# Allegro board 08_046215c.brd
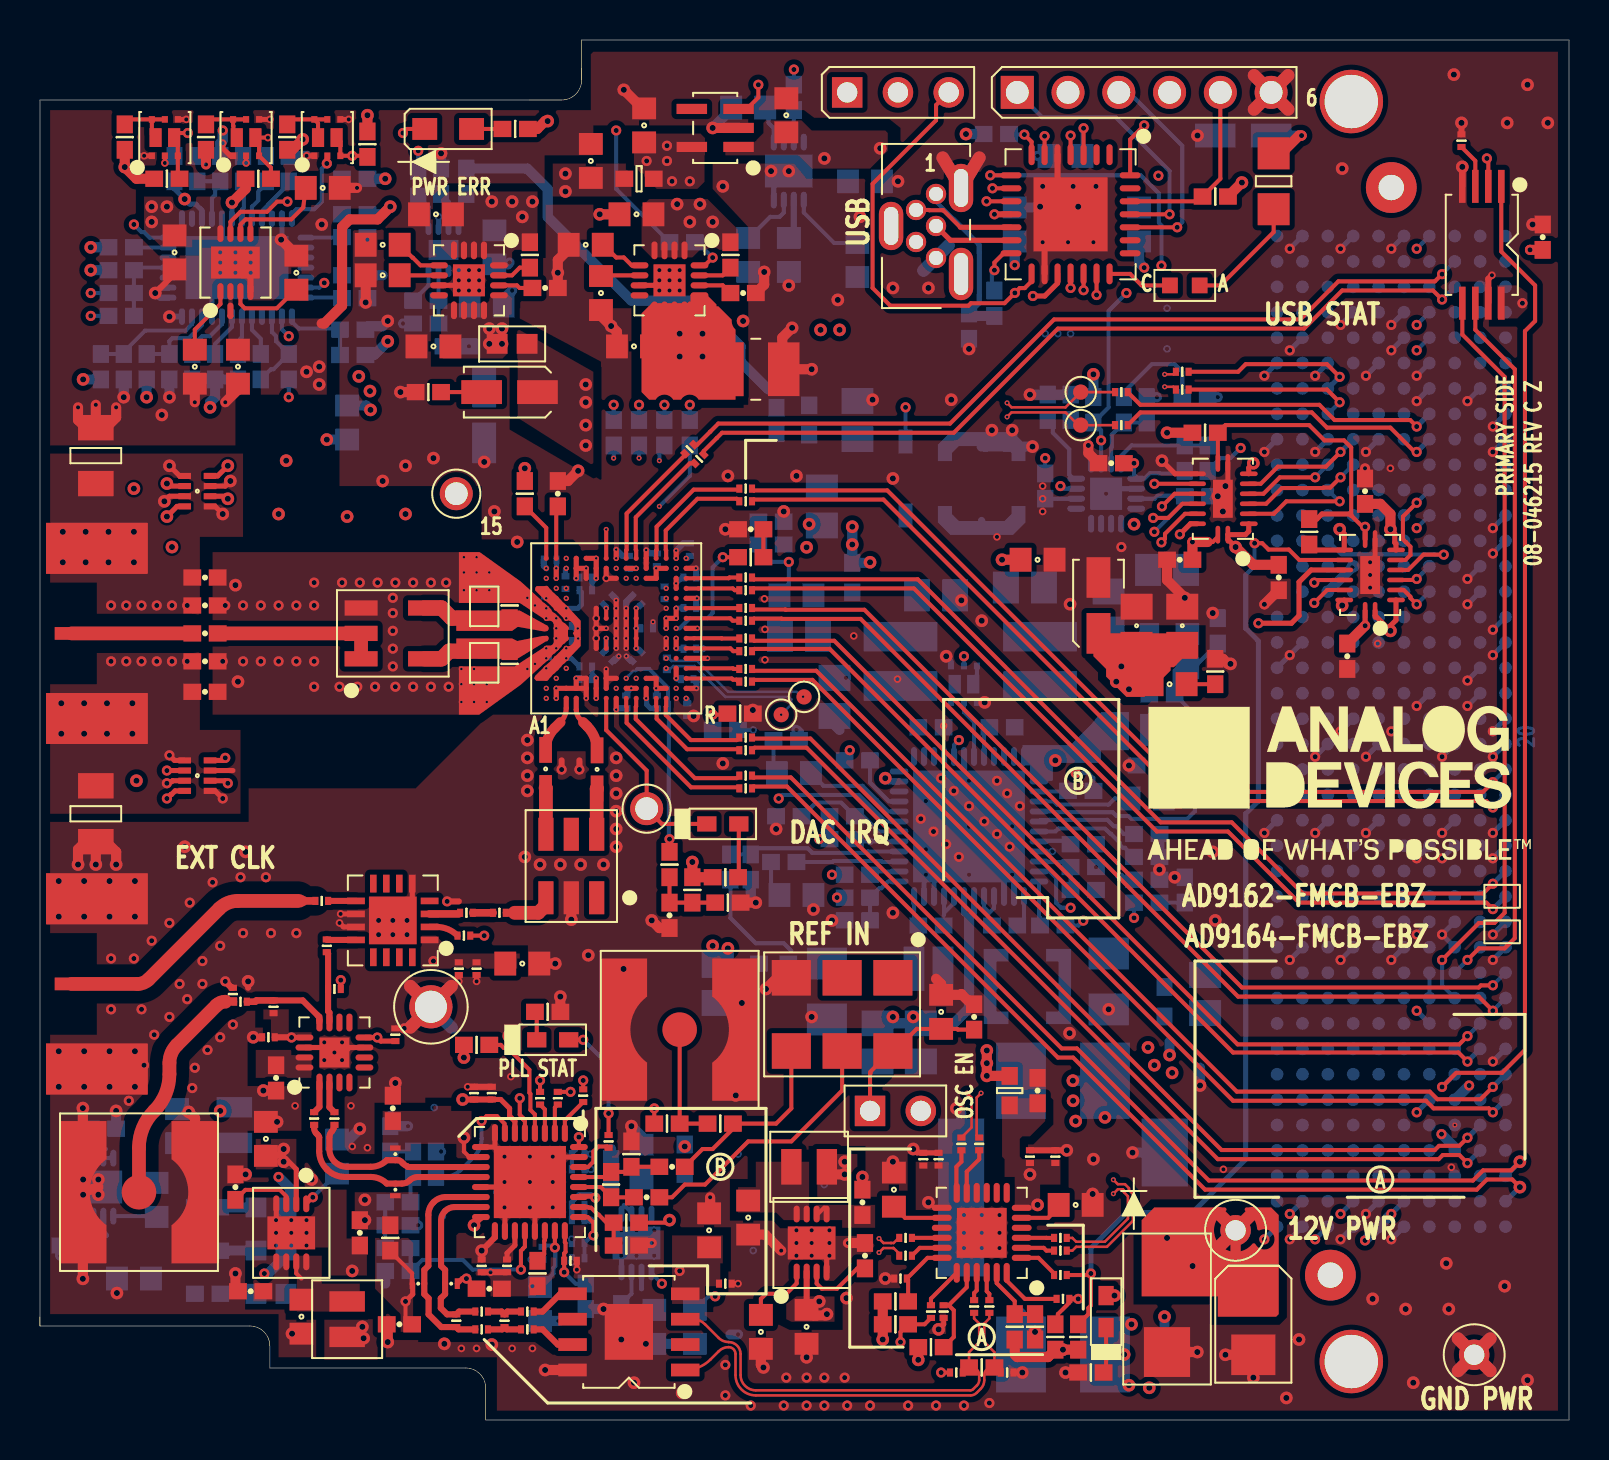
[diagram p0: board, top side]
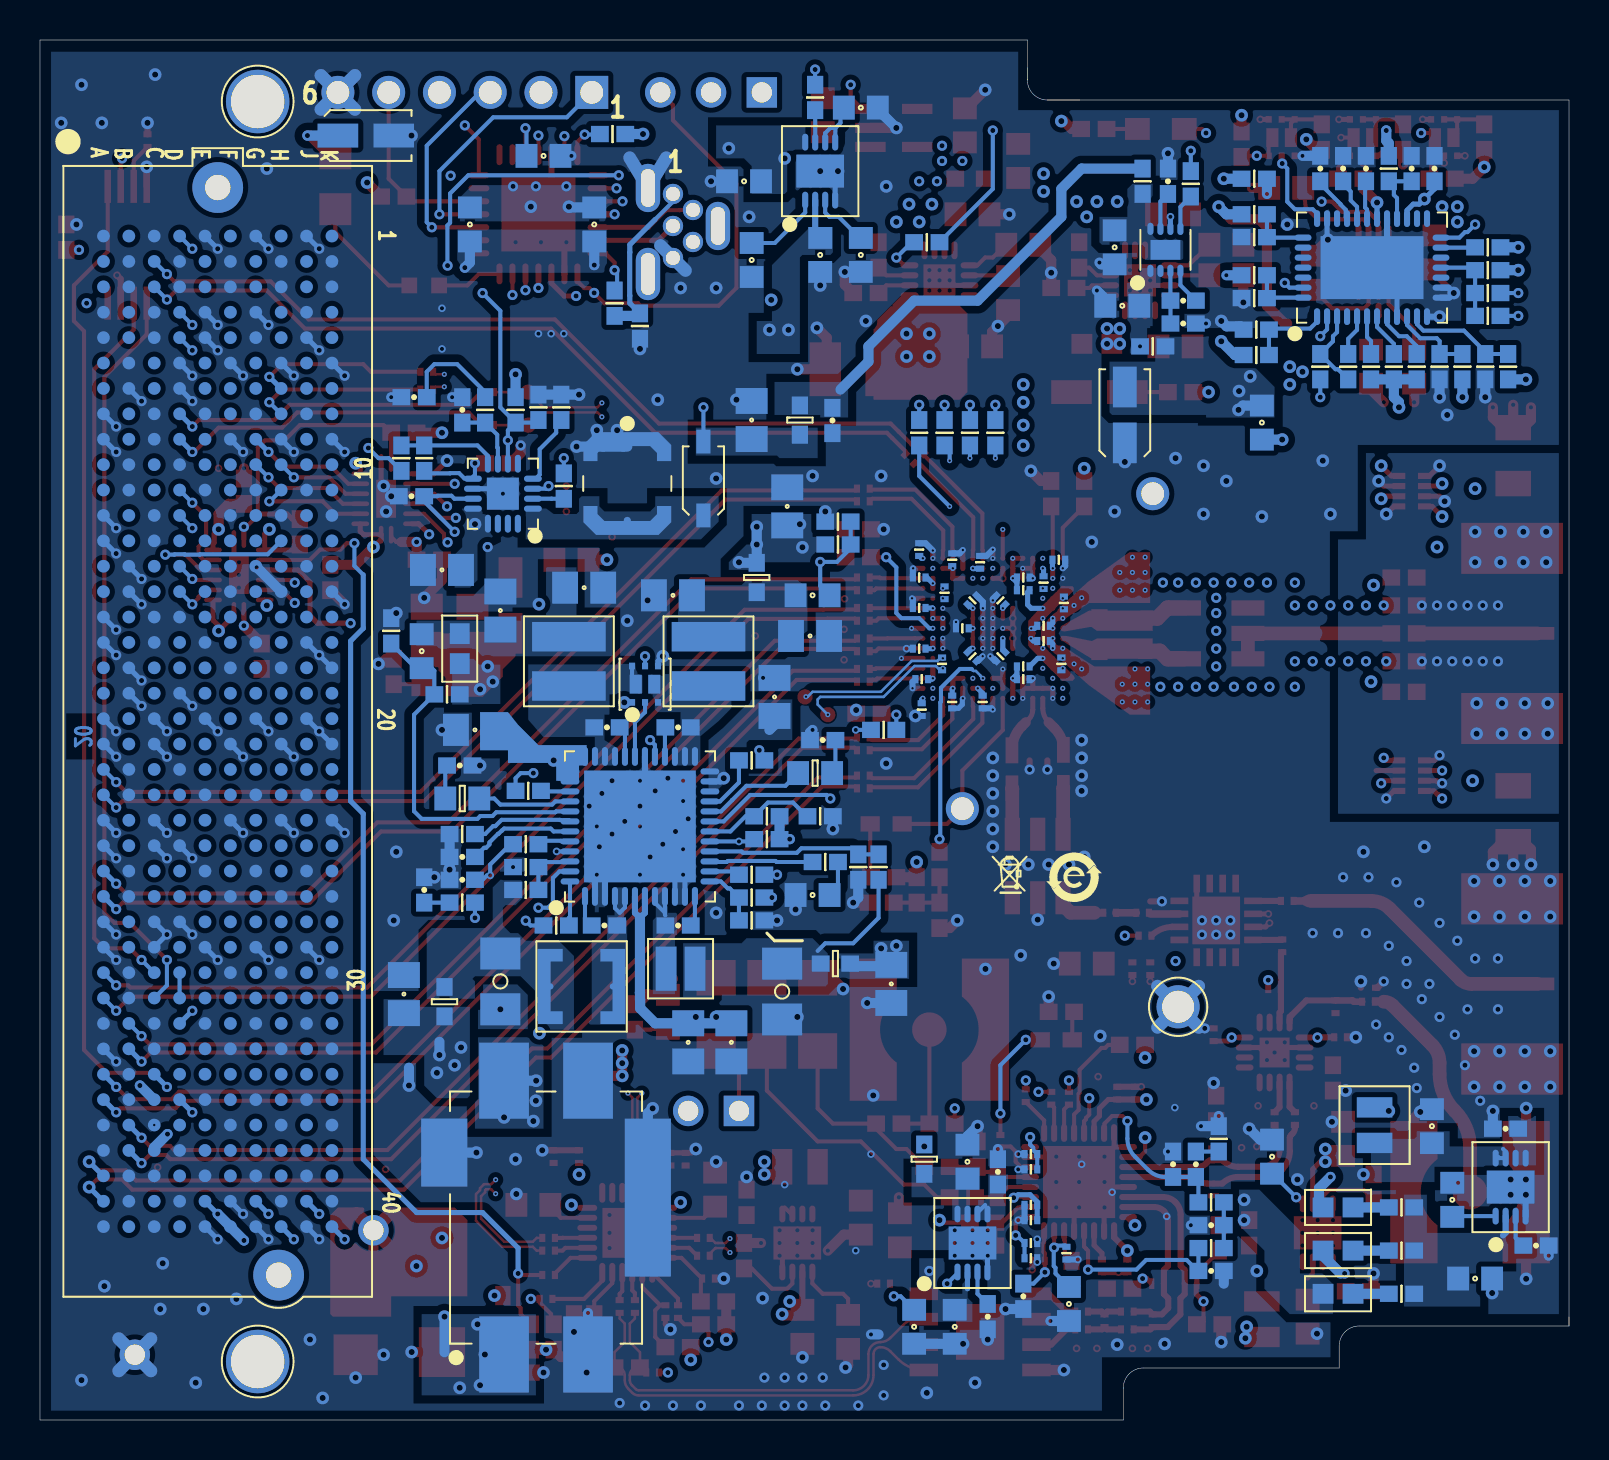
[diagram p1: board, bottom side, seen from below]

Outline 76.5 x 69 mm; copper layers: TOP, L2_GROUND, L3_SIGNAL, L4_GROUND, L5_POWER, L6_POWER, L7_GROUND, L8_POWER, L9_GROUND, L10_SIGNAL, L11_GROUND, BOTTOM. Coordinates in mm from the lower left corner of the outline.
Outline path: 26.1,66 0,66 0,4.7 ; 0,4.7 0,5.16 ; 0,4.7 10.5,4.7 arc(11.21,4.41) 11.5,3.7 11.5,2.6 21.3,2.6 arc(22.01,2.31) 22.3,1.6 22.3,0 76.5,0 76.5,69 27.1,69 27.1,67 ; 24.5,66 24.5,66 26.1,66 arc(26.81,66.29) 27.1,67 27.1,67.6

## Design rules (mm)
constraint set DEFAULT: min track width 0.203, pair gap 0.203
net group ADF4355OUTA: nets ADF4355OUTA ADF4355OUTAB
net group ADF4355OUTB: nets ADF4355OUTB ADF4355OUTBB
net group CLK: nets CLK_N CLK_P
net group DP2: nets UNNAMED_5_CAP_I292_N1 UNNAMED_5_CAP_I293_N1
net group DP5: nets UNNAMED_5_CAP_I90_N1 UNNAMED_5_CAP_I294_N1
net group GBTCLK0_M2C: nets GBTCLK0_M2C_N GBTCLK0_M2C_P
net group HMC365OUT: nets HMC365OUT HMC365OUTB
net group OUT: nets OUT_N OUT_P
net group SERDIN0_N: nets SERDIN0_N UNNAMED_7_CAP_I176_N2
net group SERDIN0_P: nets SERDIN0_P UNNAMED_7_CAP_I177_N2
net group SERDIN1_N: nets SERDIN1_N UNNAMED_7_CAP_I166_N2
net group SERDIN1_P: nets SERDIN1_P UNNAMED_7_CAP_I167_N2
net group SERDIN2_N: nets SERDIN2_N UNNAMED_7_CAP_I168_N2
net group SERDIN2_P: nets SERDIN2_P UNNAMED_7_CAP_I169_N2
net group SERDIN3_N: nets SERDIN3_N UNNAMED_7_CAP_I170_N2
net group SERDIN3_P: nets SERDIN3_P UNNAMED_7_CAP_I171_N2
net group SERDIN4_N: nets SERDIN4_N UNNAMED_7_CAP_I162_N2
net group SERDIN4_P: nets SERDIN4_P UNNAMED_7_CAP_I163_N2
net group SERDIN5_N: nets SERDIN5_N UNNAMED_7_CAP_I173_N2
net group SERDIN5_P: nets SERDIN5_P UNNAMED_7_CAP_I172_N2
net group SERDIN6_N: nets SERDIN6_N UNNAMED_7_CAP_I164_N2
net group SERDIN6_P: nets SERDIN6_P UNNAMED_7_CAP_I165_N2
net group SERDIN7_N: nets SERDIN7_N UNNAMED_7_CAP_I175_N2
net group SERDIN7_P: nets SERDIN7_P UNNAMED_7_CAP_I174_N2
net group SYNC: nets SYNC_N SYNC_P
net group SYSREF: nets SYSREF_N SYSREF_P
net group SYSREF2: nets SYSREF2_N SYSREF2_P
net group UNNAMED_3_CAP_I1318_N1: nets UNNAMED_3_CAP_I1318_N1 UNNAMED_3_CAP_I1318_N2
nets with their own width: min track width 0.203; nets ADF4355_VDD_3V3 ADF4355_VRF_3V3 UNNAMED_4_ADP5054_I1011_VDD USB_VCC
nets with their own width: min track width 0.254; nets USB_D+ USB_D-

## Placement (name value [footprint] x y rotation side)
C1  1000pF  [C0402]  8.26 42.12 0 top
C2  0.1uF  [C0201]  29.84 40.98 135 bottom
C3  0.1uF  [C0201]  28.45 40.98 45 bottom
C4  100pF  [C0201]  10.03 20.92 180 top
C5  1000pF  [C0402]  8.26 36.41 0 top
C6  4.7uF  [C0603]  37.34 65.24 90 top
C7  1uF  [C0402]  31.5 25.23 270 top
C8  0.1uF  [C0201]  26.29 41.87 90 bottom
C9  4.7uF  [C0603]  30.23 64.73 90 top
C10  0.1uF  [C0402]  48.13 34.63 0 bottom
C11  0.0033uF  [C0603]  57.4 38.44 90 bottom
C12  47uF  [C0805H60]  49.28 41.62 180 bottom
C13  0.0033uF  [C0603]  37.85 41.24 0 bottom
C14  1000pF  [C0402]  8.26 39.33 0 top
C15  47uF  [C0805H60]  44.83 41.24 0 bottom
C16  10uF  [C0805]  57.15 39.71 270 top
C17  10uF  [C0805]  54.86 39.71 270 top
C18  22uF  [C0603]  56.52 36.79 0 top
C19  22uF  [C0805]  39.12 45.68 90 bottom
C20  0.1uF  [C0201]  32.51 42.12 0 bottom
C21  1uF  [C0402]  35.56 44.54 180 top
C22  0.01UF  [C0402]  25.27 56.6 0 top
C23  1uF  [C0402]  25.91 46.32 90 top
C24  0.01UF  [C0402]  35.18 56.35 0 top
C25  1uF  [C0603]  17.14 58.76 180 top
C26  0.1uF  [C0201]  30.86 35.9 270 bottom
C27  1uF  [C0603]  27.3 58.76 180 top
C28  10uF  [C0603]  19.81 60.29 180 top
C29  10uF  [C0603]  29.84 60.29 180 top
C30  1uF  [C0603]  17.14 57.24 180 top
C31  0.1uF  [C0201]  32.51 40.6 0 bottom
C32  0.047uF  [C0508IDC]  7.87 32.22 90 top
C33  0.047uF  [C0508IDC]  7.87 46.44 270 top
C34  100pF  [C0201]  14.1 25.95 0 top
C35  1000pF  [C0402]  8.26 37.93 0 top
C36  1000pF  [C0402]  8.26 40.73 0 top
C37  0.1uF  [C0201]  32.51 38.57 0 bottom
C38  100pF  [C0201]  21.34 25.36 180 top
C39  100pF  [C0201]  14.35 23.71 90 top
C40  1uF  [C0603]  28.07 56.35 270 top
C41  10uF  [C0805]  54.74 34.5 180 bottom
C42  10uF  [C0805]  39.75 36.16 270 bottom
C43  0.1uF  [C0201]  32.39 37.04 0 bottom
C44  10uF  [C0805]  44.07 18.88 90 bottom
C45  10uF  [C0805]  41.91 18.88 90 bottom
C46  0.039uF  [C0603]  37.85 26.25 180 bottom
C47  0.018uF  [C0402]  55.5 32.73 0 bottom
C48  0.0047uF  [C0402]  37.34 34 180 bottom
C49  0.018uF  [C0402]  57.28 26.5 270 bottom
C50  10uF  [C0603]  19.69 53.68 180 top
C51  10uF  [C0603]  7.75 52.67 270 top
C52  10uF  [C0603]  29.72 53.68 180 top
C53  47uF  [C0805H60]  53.47 40.47 90 bottom
C54  47uF  [C0805H60]  37.97 39.2 180 bottom
C55  1uF  [C0603]  12.83 57.36 90 top
C56  10uF  [C0603]  6.73 58.38 270 top
C57  1UF  [C0402]  7.87 62.57 90 bottom
C58  1UF  [C0402]  6.73 62.57 90 bottom
C59  4.7uF  [C0603]  27.56 62.95 90 top
C60  2.2uF  [C0402]  11.3 62.57 90 bottom
C61  0.0012uF  [C0402]  19.81 12.79 270 bottom
C62  0.039uF  [C0402]  18.67 12.79 90 bottom
C63  100pF  [C0402]  46.74 20.15 270 top
C64  0.022uF  [C0402]  10.16 62.57 90 bottom
C65  1uF  [C0603]  45.09 20.41 270 top
C66  390pF  [C0402]  17.91 9.74 180 bottom
C67  0.047uF  [C0402]  12.45 62.57 90 bottom
C69  10pF  [C0402]  17.91 7.45 0 bottom
C71  0.1uF  [C0402]  66.29 46.44 90 top
C72  0.1uF  [C0402]  61.98 42.12 270 top
C76  0.1uF  [C0402]  57.02 43.01 180 top
C77  100pF  [C0402]  65.41 38.19 270 top
C81  0.1uF  [C0201]  35.31 46.57 0 top
C82  0.1uF  [C0201]  35.31 45.93 0 top
C83  0.1uF  [C0201]  35.31 42.12 0 top
C84  0.1uF  [C0201]  35.31 41.49 0 top
C85  0.1uF  [C0201]  35.31 40.6 0 top
C86  0.1uF  [C0201]  35.31 39.97 0 top
C87  0.1uF  [C0201]  35.31 37.55 0 top
C88  0.1uF  [C0201]  35.31 36.92 0 top
C89  0.1uF  [C0201]  35.31 32.22 0 top
C310  10uF  [C0603]  32.77 4.66 90 bottom
C311  100pF  [C0201]  21.84 22.57 90 top
C312  1uF  [C0402]  29.08 5.17 90 bottom
C313  10uF  [C0603]  30.1 12.91 270 bottom
C314  0.1uF  [C0201]  20.95 22.57 270 top
C315  1uF  [C0402]  28.57 12.41 270 bottom
C316  0.47uF  [C0603]  24.13 22.82 0 top
C317  10uF  [C0603]  30.73 4.66 90 bottom
C323  1uF  [C0402]  49.91 16.47 270 top
C325  0.47uF  [C0603]  51.82 10.76 180 top
C326  0.47uF  [C0603]  42.72 11.52 90 top
C327  0.1uF  [C0201]  44.2 13.04 90 top
C328  0.1uF  [C0201]  44.96 13.04 90 top
C330  0.1uF  [C0201]  50.8 13.17 90 top
C331  0.1uF  [C0201]  49.53 13.17 90 top
C333  0.1uF  [C0201]  51.05 8.47 0 top
C334  0.1uF  [C0201]  51.05 9.1 0 top
C338  10uF  [C0603]  33.48 9.49 270 top
C339  0.001uF  [C0201]  34.29 6.82 0 top
C340  100pF  [C0201]  47.5 5.68 90 top
C341  100pF  [C0201]  46.74 5.68 90 top
C344  0.1uF  [C0201]  46.99 13.8 90 top
C345  0.1uF  [C0201]  46.1 13.8 90 top
C346  0.1uF  [C0201]  43.31 9.1 180 top
C347  0.1uF  [C0201]  43.31 8.22 180 top
C348  2400PF  [C0803H60]  25.3 32.55 90 top
C349  2400PF  [C0803H60]  27.87 32.53 90 top
C410  1uF  [C0402]  55.37 27.01 180 bottom
C411  1uF  [C0402]  55.37 28.15 180 bottom
C412  0.1uF  [C0402]  44.58 34.63 180 bottom
C413  0.1uF  [C0402]  48.26 24.73 180 bottom
C415  0.1uF  [C0402]  44.58 24.73 0 bottom
C419  22uF  [C0805]  33.91 21.8 90 bottom
C420  22uF  [C0805]  58.29 21.3 270 bottom
C424  22uF  [C0805]  40.89 50 270 bottom
C426  4.7uF  [C0603]  22.73 58.63 270 bottom
C427  1UF  [C0402]  20.07 61.94 270 bottom
C429  1UF  [C0402]  53.59 47.84 0 top
C430  1UF  [C0402]  57.91 46.19 180 bottom
C432  4.7uF  [C0603]  22.35 55.71 180 bottom
C433  2.2uF  [C0805]  56.39 42.51 0 bottom
C434  1UF  [C0402]  19.3 55.97 0 bottom
C435  1UF  [C0402]  19.3 54.82 180 bottom
C436  1uF  [C0402]  55.37 50.51 90 bottom
C437  0.047uF  [C0402]  57.79 51.14 0 bottom
C443  47uF  [C1206]  53.47 21.93 90 bottom
C444  47UF  [C1206H71]  39.37 21.42 90 bottom
C446  4.7UF  [C0402]  36.85 49.98 90 bottom
C510  1uF  [C0603]  14.15 61.61 180 top
C513  10uF  [C0603]  9.91 52.67 90 top
C514  10uF  [C0603]  40.89 58 270 bottom
C515  1uF  [C0603]  35.43 58.25 270 bottom
C516  10uF  [C0603]  41.28 61.94 0 bottom
C518  1uF  [C0603]  35.43 65.62 0 bottom
C522  10uF  [C0603]  37.47 58.25 90 bottom
C525  10uF  [C0603]  49.91 43.01 0 top
C526  10uF  [C3216]  23.5 51.4 180 top
C531  0.1uF  [C0201]  25.4 37.81 270 bottom
C532  0.1uF  [C0201]  29.34 35.9 90 bottom
C533  0.1uF  [C0201]  27.3 37.68 180 bottom
C534  0.1uF  [C0201]  25.27 40.85 90 bottom
C535  0.1uF  [C0201]  30.86 43.01 270 bottom
C536  0.1uF  [C0201]  27.3 41.49 180 bottom
C537  0.1uF  [C0201]  26.29 39.71 0 bottom
C538  0.1uF  [C0201]  28.45 38.19 315 bottom
C539  0.1uF  [C0201]  27.3 42.12 180 bottom
C541  0.1uF  [C0201]  29.46 42.89 270 bottom
C543  0.1uF  [C0201]  26.29 38.95 0 bottom
C544  0.1uF  [C0201]  30.35 39.58 0 bottom
C545  0.1uF  [C0201]  27.3 37.04 180 bottom
C546  0.1uF  [C0201]  32.39 35.52 90 bottom
C548  47UF  [C3528]  60.71 4.79 270 top
C549  0.47uF  [C0603]  15.37 49.87 90 bottom
C550  0.1uF  [C0201]  29.84 38.19 225 bottom
C554  0.1uF  [C0201]  32.51 43.52 90 bottom
C558  0.1uF  [C0201]  25.53 43.01 180 bottom
C564  47uF  [C3216]  52.96 40.73 90 top
C566  47uF  [C3216]  22.23 50.25 90 bottom
C567  47UF  [C1210-2]  35.81 52.54 0 top
C610  1000pF  [C0402]  30.35 11.14 180 top
C611  1000pF  [C0402]  31.62 12.66 180 top
C612  0.1uF  [C0201]  26.92 13.3 0 bottom
C614  0.1uF  [C0201]  26.92 9.99 0 bottom
C616  10pF  [C0201]  26.92 10.76 0 bottom
C617  10pF  [C0201]  26.92 12.53 0 bottom
C618  10pF  [C0201]  22.61 16.34 90 top
C619  0.1uF  [C0201]  21.72 16.34 90 top
C620  10pF  [C0201]  26.92 8.09 180 bottom
C622  0.1uF  [C0201]  26.92 8.85 180 bottom
C623  120pF  [C0402]  16 9.36 270 top
C626  120pF  [C0402]  17.65 15.58 90 top
C628  120pF  [C0402]  22.48 6.56 0 top
C631  120pF  [C0402]  17.98 4.79 180 top
C632  100pF  [C0201]  14.73 15.07 90 top
C633  100pF  [C0201]  13.72 15.07 90 top
C636  10pF  [C0201]  22.1 7.71 270 top
C637  10pF  [C0201]  26.54 7.96 0 top
C638  100pF  [C0201]  24.38 4.53 0 top
C639  100pF  [C0201]  24.38 5.42 0 top
C643  10pF  [C0201]  23.37 7.71 270 top
C645  0.1uF  [C0402]  27.3 6.18 90 bottom
C648  10pF  [C0201]  25.15 8.34 270 bottom
C649  0.1uF  [C0402]  11.81 17.11 90 top
C651  4.7uF  [C0603]  25.02 5.8 90 bottom
C654  0.1uF  [C0201]  17.78 19.26 90 top
C655  0.1uF  [C0201]  11.43 19.14 180 top
C656  10uF  [C0603]  36.07 4.41 90 top
C657  10uF  [C0603]  14.86 13.17 270 bottom
C658  10uF  [C0603]  5.84 11.01 270 bottom
C659  1uF  [C0402]  41.28 8.22 270 top
C660  1uF  [C0402]  9.78 11.64 270 top
C661  1uF  [C0402]  1.65 8.72 0 bottom
C662  10uF  [C0603]  35.43 10.12 90 top
C663  10uF  [C0603]  13.08 5.17 90 top
C664  10uF  [C0603]  6.86 14.69 270 bottom
C665  1uF  [C0402]  41.15 10.88 270 top
C666  1uF  [C0402]  10.54 6.44 0 top
C667  1uF  [C0402]  3.18 14.57 180 bottom
C668  10uF  [C0603]  38.35 4.66 90 top
C669  10uF  [C0603]  11.3 14.06 270 top
C670  10uF  [C0603]  4.7 7.07 0 bottom
C810  0.1uF  [C0201]  35.31 31.58 0 top
C811  0.1uF  [C0201]  35.31 39.08 0 top
C812  0.1uF  [C0201]  35.31 38.44 0 top
C813  0.1uF  [C0201]  35.31 34.12 0 top
C814  0.1uF  [C0201]  35.31 33.49 0 top
C815  0.1uF  [C0201]  32.5 48.54 45 top
C816  0.1uF  [C0201]  32.98 48.06 45 top
C818  0.1uF  [C0402]  75.18 59.14 270 top
CR5  LTST-C190CKT  [LED0603]  34.16 29.81 0 top
D1  S1AB-13-F  [SMB-4]  56.39 5.55 270 top
D42  B0540W-7-F  [SOD123-3]  43.31 47.08 90 bottom
DS1  597-3003-407F  [LED0805]  20.42 64.55 0 top
DS2  SML-310MTT86  [LED0603]  53.34 5.42 90 top
DS61  SML-310MTT86  [LED0603]  25.65 19.01 0 top
E1  470OHM  [L0603]  40.64 42.12 90 bottom
E2  470OHM  [L0603]  56.26 20.92 270 bottom
E3  470OHM  [L0603]  36.7 22.82 180 bottom
E4  470OHM  [L0603]  29.97 62.06 180 top
E5  120OHM  [L0402]  17.53 9.1 270 top
E6  270nH  [L0402-2]  22.23 37.86 270 top
E7  270nH  [L0402-2]  22.23 40.68 270 top
E8  70OHM AT 100MEGHZ  [L0603H28]  55.5 38.57 270 bottom
E9  26OHM AT 100MEGHZ  [L0603H28]  23.62 53.81 0 top
E31  470OHM  [L0603]  32.26 13.04 270 bottom
E32  470OHM  [L0603]  48.51 16.47 90 top
E49  470OHM  [L0603]  38.48 50 270 bottom
E66  70OHM AT 100MEGHZ  [L0603H28]  11.56 10.63 0 bottom
E67  70OHM AT 100MEGHZ  [L0603H28]  11.56 6.31 0 bottom
E68  70OHM AT 100MEGHZ  [L0603H28]  11.56 8.47 0 bottom
FL1  BNX024H01  [FLSML476W358H146]  51.18 10.12 90 bottom
J31  142-0701-851  [CNSMAL562W375H166]  2.67 21.8 180 top
J32  142-0701-851  [CNSMAL562W375H166]  2.67 39.33 180 top
J61  142-0711-201  [CNJOHNSON142-0711-201]  32 19.52 0 top
J62  142-0711-201  [CNJOHNSON142-0711-201]  4.95 11.39 0 top
JP1  69157-102  [CNBERG69157-102]  41.53 15.45 0 top
JP31  0  [R0201]  57.15 52.41 0 top
JP32  0  [R0201]  57.15 51.52 0 top
JP33  0  [R0201]  54.1 51.4 0 top
JP34  0  [R0201]  54.1 49.74 0 top
L1  2.7UH  [LSML133W118H79]  9.73 14.74 270 bottom
L2  2.7UH  [LSML133W118H79]  38.48 12.66 180 top
L3  270uH  [L1210]  2.79 48.22 90 top
L4  270uH  [L1210]  2.79 30.31 270 top
L5  2.7UH  [LSML133W118H79]  15.37 5.04 90 top
L6  1.5uH  [LSMSQ157H83]  50.04 37.93 90 bottom
L7  1.5uH  [LSMSQ157H83]  43.05 37.93 90 bottom
L42  3.3uH  [LSML75W79H39]  44.45 22.57 180 bottom
L44  6.8UH  [LSMSQ130H55]  49.4 21.68 0 bottom
L45  15uH  [LSMSQ154H71]  47.12 46.82 270 bottom
L61  7.4nH  [L0302CS]  17.78 13.3 270 top
L62  7.4nH  [L0302CS]  17.78 11.52 270 top
L63  7.4nH  [L0302CS]  18.92 6.82 0 top
L64  7.4nH  [L0302CS]  20.57 6.82 0 top
NOREF  -  []  76.45 -0.04 90 top
NOREF#2  -  []  22.3 0 90 top
NOREF#3  -  []  -107.06 -243.88 0 top
NOREF#4  -  []  84.07 76.54 0 top
NOREF#5  -  []  61.47 30.57 0 top
NOREF#6  -  []  -80.52 -32.3 0 top
NOREF#7  -  []  0 4.79 0 top
NOREF#8  -  []  0 66 0 top
NOREF#9  -  []  76.5 0 90 top
NOREF#10  -  []  0 66 0 top
NOREF#11  -  []  -7.62 76.54 0 top
NOREF#12  -  []  40.13 92.54 0 top
NOREF#13  -  []  161.93 110.45 0 top
NOREF#14  -  []  22.3 0 90 top
NOREF#15  -  []  92.99 -69 0 top
NOREF#16  -  []  0 66 270 top
NOREF#17  -  []  76.5 0 90 top
NOREF#18  -  []  -94.62 -230.54 0 top
NOREF#19  -  []  -7.62 -2.96 0 top
NOREF#20  -  []  65.61 2.92 0 top
NOREF#21  -  []  76.45 68.92 180 top
NOREF#22  -  []  -94.49 -230.5 0 top
NOREF#23  -  [unnamed#2]  65.61 65.92 0 bottom
NOREF#24  -  []  24.77 27.14 180 bottom
NOREF#25  -  [unnamed#2]  65.61 2.92 0 bottom
NOREF#26  -  []  27.94 27.27 180 bottom
P1  ASP-134488-01  [CNSAMTECASP-134488-01]  73.32 59.2 270 bottom
P2  22-28-4033  [CNMOLEX22-28-4033]  40.39 66.38 0 top
Q1  SIA906EDJ-T1-GE3  [POWERPAKSC70-6]  46.23 36.79 180 bottom
Q2  SIA906EDJ-T1-GE3  [POWERPAKSC70-6]  6.25 64.12 0 top
Q3  SIA906EDJ-T1-GE3  [POWERPAKSC70-6]  10.31 64.12 0 top
Q4  SIA906EDJ-T1-GE3  [POWERPAKSC70-6]  14.38 64.12 0 top
R1  100K  [R0402]  36.58 44.92 0 bottom
R2  88.7K  [R0402]  36.58 43.78 0 bottom
R3  0  [R0402]  34.42 25.87 0 top
R4  1K  [R0402]  31.5 27.77 270 top
R5  10K  [R0402]  32.64 26.5 270 top
R6  1K  [R0402]  34.29 27.14 0 top
R7  9.76K  [R0402]  24.26 46.32 90 top
R8  0  [R0402]  35.03 35.32 180 top
R9  100K  [R0402]  46.48 54.7 270 bottom
R10  100K  [R0402]  47.75 55.84 270 bottom
R11  200  [R0201]  20.83 4.96 90 top
R12  62  [R0201]  22.1 4.53 0 top
R13  62  [R0201]  22.1 5.42 0 top
R14  200  [R0201]  23.24 4.96 90 top
R15  100K  [R0402]  58.93 39.46 270 bottom
R16  49.9K  [R0402]  56.13 36.28 180 bottom
R17  0.2  [R0402]  58.8 37.43 90 top
R18  0  [R0402]  34.29 34.5 180 bottom
R19  0  [R0402]  28.7 49.36 270 bottom
R20  0  [R0402]  29.97 49.36 270 bottom
R21  1  [R0402]  35.56 43.14 180 top
R22  0  [R0402]  32.51 49.36 270 bottom
R23  0  [R0402]  31.24 49.36 270 bottom
R24  100K  [R0402]  24.51 58.25 270 top
R25  100K  [R0402]  34.54 58.25 270 top
R26  100  [R0201]  31.24 41.36 90 bottom
R27  0.1  [R0402]  19.43 51.4 180 top
R28  10K  [R0402]  47.85 64.3 180 bottom
R29  10K  [R0402]  12.37 64.15 90 top
R30  10K  [R0402]  4.24 64.15 90 top
R31  0  [R0201]  21.21 24.22 0 top
R32  100  [R0201]  31.37 37.81 270 bottom
R33  49.9  [R0402]  23.5 37.81 90 top
R34  49.9  [R0402]  23.5 40.73 90 top
R35  10K  [R0402]  42.8 4.79 180 top
R36  10K  [R0402]  50.8 4.15 270 top
R37  100  [R0402]  47.12 2.63 180 top
R38  10K  [R0402]  51.94 4.15 270 top
R39  10K  [R0402]  48.77 4.66 270 top
R40  10K  [R0402]  8.31 64.15 90 top
R41  0  [R0402]  37.47 30.19 0 bottom
R42  0  [R0402]  40.89 24.98 180 bottom
R43  2.87K  [R0402]  37.21 27.9 0 bottom
R44  6.98K  [R0603]  55.37 31.08 180 bottom
R45  1.15K  [R0603]  37.72 32.35 0 bottom
R46  5.9K  [R0402]  55.37 25.87 180 bottom
R47  0  [R0402]  52.07 31.46 0 bottom
R48  0  [R0402]  40.13 30.19 180 bottom
R49  0  [R0402]  40.89 26.12 180 bottom
R50  10K  [R0402]  6.35 62.06 180 top
R51  10K  [R0402]  10.92 62.06 180 top
R52  10K  [R0402]  16.38 63.79 90 top
R53  3.3K  [R0402]  4.06 58.63 0 bottom
R54  0  [R0402]  9.02 62.57 270 bottom
R55  0  [R0402]  15.65 53.25 0 bottom
R56  24.3K  [R0402]  9.91 52.67 270 bottom
R57  9.53K  [R0402]  7.62 52.67 270 bottom
R58  95.3K  [R0402]  8.76 52.67 270 bottom
R59  182K  [R0402]  15.75 60.29 180 bottom
R60  49.9K  [R0402]  15.75 59.14 0 bottom
R61  1.8K  [R0402]  17.53 14.06 270 bottom
R62  3.3K  [R0402]  17.91 10.88 180 bottom
R63  0  [R0402]  15.75 62.06 180 bottom
R64  0  [R0402]  17.91 8.6 0 bottom
R65  0  [R0402]  34.04 14.82 180 top
R66  261K  [R0402]  15.75 57.24 180 bottom
R67  49.9K  [R0402]  15.75 56.09 0 bottom
R68  0  [R0402]  4.06 57.49 0 bottom
R69  51  [R0402]  29.59 13.3 270 top
R70  0  [R0402]  4.06 55.21 180 bottom
R71  0  [R0402]  4.06 56.35 180 bottom
R72  10K  [R0402]  63.5 44.41 90 top
R73  10K  [R0402]  58.29 49.36 0 top
R74  62K  [R0402]  12.45 52.67 90 bottom
R75  66.5K  [R0402]  11.05 52.67 90 bottom
R76  0  [R0402]  15.65 54.52 0 bottom
R77  0  [R0402]  5.33 52.67 90 bottom
R78  0  [R0402]  6.48 52.67 270 bottom
R79  0  [R0402]  3.05 52.67 90 bottom
R80  0  [R0402]  4.19 52.67 270 bottom
R88  20K  [R0201]  71.12 63.97 270 top
R310  0  [R0201]  45.21 5.42 90 top
R311  0  [R0201]  43.05 7.07 0 top
R312  10K  [R0402]  42.8 5.93 0 top
R313  10K  [R0402]  44.58 3.64 0 top
R314  0  [R0201]  44.58 5.42 90 top
R315  0  [R0201]  51.18 6.06 180 top
R316  0  [R0201]  51.05 7.25 180 top
R327  1K  [R0402]  23.77 64.55 180 top
R328  0  [R0201]  48.39 2.37 180 top
R329  0  [R0201]  45.85 2.37 0 top
R330  10K  [R0402]  49.78 4.66 270 top
R332  0  [R0201]  22.99 25.36 0 top
R337  0  [R0402]  18.92 61.81 270 bottom
R338  0  [R0402]  32.13 58.89 0 bottom
R339  0  [R0402]  37.72 66.13 270 bottom
R410  0  [R0402]  40.89 32.98 180 bottom
R411  0  [R0402]  50.67 24.73 0 bottom
R412  0  [R0402]  40.89 27.27 180 bottom
R413  31.6K  [R0402]  55.37 29.3 0 bottom
R414  0  [R0402]  52.2 28.79 180 bottom
R416  10K  [R0402]  40.13 29.04 180 bottom
R417  680  [R0402]  52.58 2.37 0 top
R419  80.6K  [R0402]  34.54 27.65 90 bottom
R420  75K  [R0402]  52.2 26.5 180 bottom
R423  13.7K  [R0402]  35.56 27.65 270 bottom
R424  20K  [R0402]  52.2 27.65 0 bottom
R425  0  [R0402]  50.29 46.7 270 bottom
R428  330K  [R0402]  52.7 50.51 270 bottom
R429  0  [R0402]  50.42 50.63 270 bottom
R430  412K  [R0402]  58.42 48.09 90 bottom
R434  110K  [R0402]  57.28 48.09 270 bottom
R436  62K  [R0402]  51.56 50.63 90 bottom
R437  1.5K  [R0402]  54.23 50.51 90 bottom
R443  0  [R0402]  21.34 61.94 270 bottom
R445  0  [R0402]  20.83 53.68 180 bottom
R611  1.8K  [R0402]  21.84 18.76 180 top
R612  100  [R0402]  28.57 11.77 270 top
R613  0  [R0201]  27.18 16.22 270 top
R614  0  [R0201]  25.91 16.09 270 top
R615  0  [R0201]  25.02 16.09 270 top
R617  0  [R0402]  29.34 8.72 0 top
R618  5.1K  [R0402]  24.89 7.33 270 top
R619  0  [R0402]  29.34 9.87 0 top
R620  0  [R0201]  28.45 13.93 90 top
R621  100  [R0402]  25.4 20.41 180 top
R622  49.9  [R0201]  11.68 20.66 90 top
R623  49.9  [R0201]  9.65 21.3 90 top
R625  49.9  [R0201]  14.73 21.55 0 top
R626  0  [R0402]  8.38 8.47 0 bottom
R627  0  [R0402]  8.38 10.63 0 bottom
R628  0  [R0402]  8.38 6.31 0 bottom
R629  0  [R0402]  31.37 14.82 180 top
SYNCN  TESTPAD  [TPSMC30]  52.07 49.74 0 top
SYNCP  TESTPAD  [TPSMC30]  52.07 51.4 0 top
SYSRFN  TESTPAD  [TPSMC30]  38.23 36.16 0 top
SYSRFP  TESTPAD  [TPSMC30]  37.08 35.27 0 top
T1  TC1-1-43A+  [AT224-1]  17.65 39.33 90 top
T33  TCM1-63AX+  [TSML150W160H160]  26.58 27.7 180 top
TP21  TESTPAD  [TPC65D45]  30.35 30.57 0 top
TP41  RED  [CNKEY5001TP]  59.82 9.49 0 top
TP42  BLK  [CNKEY5005-9TP]  19.56 20.66 0 top
TP43  TESTPAD  [TPC65D45]  20.83 46.32 0 top
TP64  BLK  [CNKEY5001TP]  71.75 3.26 0 top
U1  AD9162BBCZ  [BGA165_A]  28.83 39.58 0 top
U2  ADP1761ACPZ-1.2  [QFN16_3X3_PAD1_6X1_6]  21.46 56.98 180 top
U3  ADP1761ACPZ-1.2  [QFN16_3X3_PAD1_6X1_6]  31.5 56.98 180 top
U4  ADM7160AUJZ-3.3  [TSOT-5]  33.78 64.6 90 top
U5  -  [HMC849LP4CE]  17.65 24.98 90 top
U6  ADM7150ACPZ-5.0-R7  [DFN8_3X3_PAD2_38X1_64]  29.84 8.85 180 bottom
U7  AD9508BCPZ  [QFN24_4X4_PAD2_5X2_5]  47.12 9.36 90 top
U8  LTC2928CUHF#PBF  [QFN38_7X5_PAD5_15X3_15]  9.86 57.62 180 bottom
U9  HMC362S8GE  [SO8NB-3-PAD]  29.46 4.41 90 top
U10  ADP5054ACPZ  [QFN48_7X7_PAD5_6X5_6]  46.48 29.68 180 bottom
U11  ADP5073ACPZ  [QFN16_3X3_PAD1_6X1_6]  53.34 46.32 90 bottom
U12  ADP7183ACPZN1.2-R7  [DFN8_2X2_PAD1_5X1]  20.19 58.51 180 bottom
U13  ADM7154ACPZ-2.5  [DFN8_3X3_PAD2_44X1_6_A]  9.78 57.87 0 top
U14  ADM7154ACPZ-3.3  [DFN8_3X3_PAD2_38X1_64]  37.47 62.44 180 bottom
U15  ADF4355BCPZ  [QFN32_5X5_PAD3_6X3_6]  24.51 11.9 180 top
U16  ADCLK914BCPZ  [QFN16_3X3_PAD1_5X1_5]  14.73 18.38 0 top
U17  ADM7150ACPZ-5.0-R7  [DFN8_3X3_PAD2_38X1_64]  38.61 8.85 0 top
U18  ADM7154ACPZ-3.3  [DFN8_3X3_PAD2_38X1_64]  12.57 9.36 180 top
U19  ADM7154ACPZ-3.3  [DFN8_3X3_PAD2_38X1_64]  2.92 11.64 180 bottom
U20  PIC18F24J50-I/ML  [QFN28_6X6_PAD3_7X3_7]  51.56 60.29 180 top
U21  FXL4TD245BQX  [DQFN16_3_5X2_5_PAD2_15X1_15]  59.18 46.06 90 top
U22  FXL4TD245BQX  [DQFN16_3_5X2_5_PAD2_15X1_15]  66.55 42.25 90 top
U23  M24C02-RDW6TP  [TSSOP8]  72.14 58.76 180 top
XC4  10uF  [C3216]  60.2 64.22 180 bottom
XC5  0.1UF  [C0603]  54.99 59.78 90 bottom
XC6  0.1UF  [C0603]  48.77 59.78 90 bottom
XC12  10uF  [C0603]  51.31 63.21 0 bottom
XCR1  LB Q39E-N1OO-35-1  [LED0603H12]  57.28 56.73 0 top
XP1  TSW-106-08-G-S  [CNBERG1X6H205LD36]  48.9 66.38 0 top
XP2  2041517-1  [CNTE2041517-1]  44.83 61.3 180 top
XR2  10K  [R0402]  58.8 61.17 180 top
XR6  330  [R1206]  61.72 61.94 270 top
Y61  120.00MEGHZ  [YSML276W197H63]  40.13 20.28 180 top

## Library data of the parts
C1 C5 C35 C36 C610 C611 = CAP: Tolerance: 5; User Part Number: UPN; alternate symbols: (C0402L_ALT); part number: CAP_SM-1000PF,50V,5,E012419,C0402; tolerance: 5
C2 C8 C20 C81-C89 C810-C816 = CAP: alternate symbols: (); part number: CAP_SM-0.1UF,6.3V,10,E011567,C0201; tolerance: 10; signal model: DEFAULT_CAPACITOR_100000pF_1_2
C3 C26 C31 C37 C43 C314 C327 C328 C330 C331 C333 C334 C344-C347 C531-C539 C541 C543-C546 C550 C554 C558 C654 C655 = CAP: alternate symbols: (); part number: CAP_SM-0.1UF,6.3V,10,E011567,C0201; tolerance: 10
C4 C34 C38 C39 C311 C340 C341 C632 C633 C638 C639 = CAP: alternate symbols: (); part number: CAP_SM-100PF,25V,10,E006763,C0201; tolerance: 10
C6 C9 = CAP: Tolerance: 10; User Part Number: UPN; alternate symbols: (); part number: CAP_SM-4.7UF,16V,10,E020112,C0603; tolerance: 10
C7 C21 = CAP: Tolerance: 10; User Part Number: UPN; alternate symbols: (); part number: CAP_SM-1UF,6.3V,10,E007449,C0402; tolerance: 10
C10 C412 C413 C415 = CAP: Tolerance: 10; User Part Number: UPN; alternate symbols: (); part number: CAP_SM-0.1UF,35V,10,E019488,C0402; tolerance: 10
C11 C13 = CAP: Tolerance: 10; User Part Number: UPN; alternate symbols: (); part number: CAP_SM-0.0033UF,50V,10,E019647,C0603; tolerance: 10
C12 C15 C53 C54 = CAP: Tolerance: 20; User Part Number: UPN; alternate symbols: (); part number: CAP_SM-47UF,10V,20,E022064,C0805H60; tolerance: 20
C14 = CAP: Tolerance: 5; User Part Number: UPN; alternate symbols: (C0402L_ALT); part number: CAP_SM-1000PF,50V,5,E012419,C0402; tolerance: 5; signal model: DEFAULT_CAPACITOR_100000pF_1_2
C16 C17 C41 C42 C44 C45 = CAP: Tolerance: 10; User Part Number: UPN; alternate symbols: (C0805_0603_TH200LD25); part number: CAP_SM-10UF,25V,10,E019080,C0805; tolerance: 10
C18 = CAP: Tolerance: 20; User Part Number: UPN; alternate symbols: (); part number: CAP_SM-22UF,6.3V,20,E021512,C0603; tolerance: 20
C19 C419 C420 C424 = CAP: Tolerance: 20; User Part Number: UPN; alternate symbols: (); part number: CAP_SM-22UF,10V,20,E020687,C0805; tolerance: 20
C22 C24 = CAP: Tolerance: 10; User Part Number: UPN; alternate symbols: (); part number: CAP_SM-0.01UF,16V,10,E024440,C0402; tolerance: 10
C23 = CAP: Tolerance: 10; User Part Number: UPN; alternate symbols: (); part number: CAP_SM-1UF,6.3V,10,E007449,C0402; tolerance: 10; signal model: DEFAULT_CAPACITOR_100000pF_1_2
C25 C27 C30 C40 C65 = CAP: Tolerance: 10; User Part Number: UPN; alternate symbols: (); part number: CAP_SM-1UF,10V,10,E011783,C0603; tolerance: 10
C28 C29 C50 C310 C313 C317 C525 C657 C662 = CAP: Tolerance: 20; User Part Number: UPN; alternate symbols: (); part number: CAP_SM-10UF,10V,20,E018646,C0603; tolerance: 20
C32 C33 = CAPARRAY8PP: Tolerance: N/A; User Part Number: UPN; alternate symbols: (); part number: CAPARRAY8PP_SM-0.047UF,N/A,N/A,E007353,C0508IDC; tolerance: N/A
C46 = CAP: Tolerance: 10; User Part Number: UPN; alternate symbols: (); part number: CAP_SM-0.039UF,16V,10,E012650,C0603; tolerance: 10
C47 C49 = CAP: Tolerance: 10; User Part Number: UPN; alternate symbols: (); part number: CAP_SM-0.018UF,16V,10,E019653,C0402; tolerance: 10
C48 = CAP: Tolerance: 5; User Part Number: UPN; alternate symbols: (); part number: CAP_SM-0.0047UF,50V,5,E006445,C0402; tolerance: 5
C51 C52 C56 C513 C514 C516 C522 C656 C658 C663 C664 C668-C670 = CAP: User Part Number: UPN; Tolerance: 20; alternate symbols: (); part number: CAP_SM-10UF,10V,20,E018646,C0603; tolerance: 20
C55 C510 C515 C518 = CAP: User Part Number: UPN; Tolerance: 10; alternate symbols: (); part number: CAP_SM-1UF,10V,10,E011783,C0603; tolerance: 10
C57 C58 = CAP: Tolerance: 10; User Part Number: UPN; alternate symbols: (C0402L_ALT); part number: CAP_SM-1UF,25V,10,E026618,C0402; tolerance: 10
C59 C426 C432 C651 = CAP: Tolerance: 10; User Part Number: UPN; alternate symbols: (); part number: CAP_SM-4.7UF,6.3V,10,E010382,C0603; tolerance: 10
C60 = CAP: Tolerance: 20; User Part Number: UPN; alternate symbols: (); part number: CAP_SM-2.2UF,6.3V,20,E012333,C0402; tolerance: 20
C61 = CAP: Tolerance: 5; User Part Number: UPN; alternate symbols: (); part number: CAP_SM-0.0012UF,25V,5,E012597,C0402; tolerance: 5
C62 = CAP: Tolerance: 10; User Part Number: UPN; alternate symbols: (); part number: CAP_SM-0.039UF,10V,10,E020705,C0402; tolerance: 10
C63 C77 = CAP: Tolerance: 5; User Part Number: UPN; alternate symbols: (C0402L_ALT); part number: CAP_SM-100PF,50V,5,E023843,C0402; tolerance: 5
C64 = CAP: Tolerance: 10; User Part Number: UPN; alternate symbols: (); part number: CAP_SM-0.022UF,25V,10,E006455,C0402; tolerance: 10
C66 = CAP: Tolerance: 5; User Part Number: UPN; alternate symbols: (); part number: CAP_SM-390PF,50V,5,E013656,C0402; tolerance: 5
C67 C437 = CAP: Tolerance: 10; User Part Number: UPN; alternate symbols: (C0402L_ALT); part number: CAP_SM-0.047UF,25V,10,E006454,C0402; tolerance: 10
C69 = CAP: Tolerance: 2; User Part Number: UPN; alternate symbols: (); part number: CAP_SM-10PF,50V,2,E015937,C0402; tolerance: 2
C71 C72 C76 = CAP: Tolerance: 10; User Part Number: UPN; alternate symbols: (); part number: CAP_SM-0.1UF,16V,10,E007200,C0402; tolerance: 10
C312 C315 C323 C659-C661 C665-C667 = CAP: Tolerance: 10; User Part Number: UPN; alternate symbols: (); part number: CAP_SM-1UF,6.3V,10,E011561,C0402; tolerance: 10
C316 C325 C326 C549 = CAP: Tolerance: 10; User Part Number: UPN; alternate symbols: (); part number: CAP_SM-0.47UF,16V,10,E012085,C0603; tolerance: 10
C338 = CAP: Tolerance: 20; User Part Number: UPN; alternate symbols: (); part number: CAP_SM-10UF,6.3V,20,E021627,C0603; tolerance: 20
C339 = CAP: alternate symbols: (); part number: CAP_SM-0.001UF,25V,10,E006762,C0201; tolerance: 10
C348 C349 = CAP: Tolerance: N/A; User Part Number: UPN; alternate symbols: (C0805H30); part number: CAP_SM-2400PF,50V,N/A,E007314,C0803H60; tolerance: N/A
C410 C411 = CAP: Tolerance: 10; User Part Number: UPN; alternate symbols: (); part number: CAP_SM-1UF,10V,10,E011429,C0402; tolerance: 10
C427 C429 C430 C434 C435 = CAP: Tolerance: 20; User Part Number: UPN; alternate symbols: (); part number: CAP_SM-1UF,16V,20,E030046,C0402; tolerance: 20
C433 = CAP: Tolerance: 10; User Part Number: UPN; alternate symbols: (); part number: CAP_SM-2.2UF,25V,10,E018423,C0805; tolerance: 10
C436 = CAP: Tolerance: 20; User Part Number: UPN; alternate symbols: (); part number: CAP_SM-1UF,16V,20,E020695,C0402; tolerance: 20
C443 = CAP: User Part Number: UPN; Tolerance: 20; alternate symbols: (); part number: CAP_SM-47UF,6.3V,20,E006154,C1206; tolerance: 20
C444 = CAP: Tolerance: 20; User Part Number: UPN; alternate symbols: (); part number: CAP_SM-47UF,16V,20,E030047,C1206H71; tolerance: 20
C446 = CAP: Tolerance: 10; User Part Number: UPN; alternate symbols: (); part number: CAP_SM-4.7UF,10V,10,E022491,C0402; tolerance: 10
C526 XC4 = CAPP: Tolerance: N/A; User Part Number: UPN; alternate symbols: (); part number: CAPP_SM-10UF,N/A,N/A,E000690,C3216; tolerance: N/A
C548 = CAPP: User Part Number: UPN; Tolerance: 20; alternate symbols: (); part number: CAPP_SM-47UF,16V,20,E027486,C3528; tolerance: 20
C564 C566 = CAPP: Tolerance: N/A; User Part Number: UPN; alternate symbols: (); part number: CAPP_SM-47UF,N/A,N/A,E019095,C3216; tolerance: N/A
C567 = CAP: Tolerance: 10; User Part Number: UPN; alternate symbols: (); part number: CAP_SM-47UF,10V,10,E030048,C1210-2; tolerance: 10
C612 C614 C619 C622 = CAP: alternate symbols: (); part number: CAP_SM-0.1UF,16V,20,E017331,C0201; tolerance: 20
C616-C618 C620 C636 C637 C643 C648 = CAP: alternate symbols: (); part number: CAP_SM-10PF,25V,5,E022849,C0201; tolerance: 5
C623 C626 = CAP: Tolerance: 5; User Part Number: UPN; alternate symbols: (); part number: CAP_SM-120PF,50V,5,E011633,C0402; tolerance: 5
C628 C631 = CAP: User Part Number: UPN; Tolerance: 5; alternate symbols: (); part number: CAP_SM-120PF,50V,5,E011633,C0402; tolerance: 5
C645 C649 C818 = CAP: Tolerance: 10; User Part Number: UPN; alternate symbols: (); part number: CAP_SM-0.1UF,10V,10,E020421,C0402; tolerance: 10
CR5 = DIOLED: Tolerance: N/A; User Part Number: UPN; alternate symbols: (); part number: DIOLED_SM-LTST-C190CKT,N/A,N/A,E023763,LED0603; tolerance: N/A
D1 = DIO: User Part Number: UPN; Tolerance: N/A; alternate symbols: (); part number: DIO_SM-S1AB-13-F,50V,N/A,E013436,SMB-4; tolerance: N/A
D42 = DIOSCHOTTKY: Tolerance: N/A; User Part Number: UPN; alternate symbols: (); part number: DIOSCHOTTKY_SM-B0540W-7-F,40V,N/A,E019694,SOD123-3; tolerance: N/A
DS1 = DIOLED: Tolerance: N/A; User Part Number: UPN; alternate symbols: (); part number: DIOLED_SM-597-3003-407F,N/A,N/A,E019308,LED0805; tolerance: N/A
DS2 DS61 = DIOLED: Tolerance: N/A; User Part Number: UPN; alternate symbols: (); part number: DIOLED_SM-SML-310MTT86,2.8V,N/A,E001179,LED0603; tolerance: N/A
E1-E4 E31 E32 E49 = FERRITE: Tolerance: 25; User Part Number: UPN; alternate symbols: (); part number: FERRITE_SM-470OHM,25,E021228,L0603; tolerance: 25
E5 = FERRITE: Tolerance: 25; User Part Number: UPN; alternate symbols: (); part number: FERRITE_SM-120OHM,25,E007371,L0402; tolerance: 25
E6 E7 = FERRITE: Tolerance: 5; User Part Number: UPN; alternate symbols: (); part number: FERRITE_SM-270NH,5,E018219,L0402-2; tolerance: 5
E8 E66-E68 = FERRITE: Tolerance: 25; User Part Number: UPN; alternate symbols: (); part number: FERRITE_SM-70OHM AT 100MEGHZ,25,E026979,L0603H28; tolerance: 25
E9 = FERRITE: Tolerance: 25; User Part Number: UPN; alternate symbols: (); part number: FERRITE_SM-26OHM AT 100MEGHZ,25,E025169,L0603H28; tolerance: 25
FL1 = FLBNX01: User Part Number: UPN; Tolerance: N/A; alternate symbols: (); part number: FLBNX01_SM-BNX024H01,E015493,FLSML476W358H146; tolerance: N/A
J31 J32 = CNBNC5P: Tolerance: N/A; User Part Number: UPN; alternate symbols: (); part number: CNBNC5P_SM-142-0701-851,E014551,CNSMAL562W375H166; tolerance: N/A
J61 J62 = CNBNC3P: User Part Number: UPN; Tolerance: N/A; alternate symbols: (); part number: CNBNC3P_SM-142-0711-201,E000902,CNJOHNSON142-0711-201; tolerance: N/A
JP1 = CNJMPRSHRT: Tolerance: N/A; User Part Number: UPN; alternate symbols: (); part number: CNJMPRSHRT_TH-69157-102,E000942,CNBERG69157-102; tolerance: N/A
JP31-JP34 R31 R310 R311 R314-R316 R328 R329 R332 R613-R615 R620 = RES: alternate symbols: (); part number: RES_SM-0,E004015,1/20W,5,R0201; tolerance: 5
L1 L2 L5 = IND: Tolerance: 10; User Part Number: UPN; alternate symbols: (); part number: IND_SM-2.7UH,10,E024365,LSML133W118H79; tolerance: 10
L3 L4 = IND: Tolerance: 5; User Part Number: UPN; alternate symbols: (); part number: IND_SM-270UH,5,E011651,L1210; tolerance: 5
L6 L7 = IND: User Part Number: UPN; Tolerance: 20; alternate symbols: (); part number: IND_SM-1.5UH,20,E017267,LSMSQ157H83; tolerance: 20
L42 = IND: Tolerance: 20; User Part Number: UPN; alternate symbols: (); part number: IND_SM-3.3UH,20,E022695,LSML75W79H39; tolerance: 20
L44 = IND: User Part Number: UPN; Tolerance: 20; alternate symbols: (); part number: IND_SM-6.8UH,20,E023029,LSMSQ130H55; tolerance: 20
L45 = IND: User Part Number: UPN; Tolerance: 20; alternate symbols: (); part number: IND_SM-15UH,20,E022692,LSMSQ154H71; tolerance: 20
L61-L64 = IND: Tolerance: 5; User Part Number: UPN; alternate symbols: (); part number: IND_SM-7.4NH,5,E021551,L0302CS; tolerance: 5
P1 = CN400P_A_K_V2: User Part Number: UPN; Tolerance: N/A; alternate symbols: (); part number: CN400P_A_K_V2_SM-ASP-134488-01,E011384,CNSAMTECASP-134488-01; tolerance: N/A
P2 = CN3P: User Part Number: UPN; Tolerance: N/A; alternate symbols: (); part number: CN3P_TH-22-28-4033,E005952,CNMOLEX22-28-4033; tolerance: N/A
Q1-Q4 = TRANNMOSFET_2PAD: Tolerance: N/A; User Part Number: UPN; alternate symbols: (); part number: TRANNMOSFET_2PAD_SM-SIA906EDJ-T1-GE3,E015819,POWERPAKSC70-6; tolerance: N/A
R1 = RES: Tolerance: 1; User Part Number: UPN; alternate symbols: (R0402L,R0402L_ALT); part number: RES_SM-100K,E003796,1/16W,1,R0402; tolerance: 1; signal model: DEFAULT_RESISTOR_0.001OHM_1_2
R2 = RES: Tolerance: 1; User Part Number: UPN; alternate symbols: (R0402L); part number: RES_SM-88.7K,E020516,1/10W,1,R0402; tolerance: 1
R3 R8 R41 R42 R47-R49 R54 R55 R63 R65 R68 R70 R71 R76-R80 R337-R339 R410-R412 R414 R425 R429 R443 R445 R617 R619 R626-R629 = RES: Tolerance: 5; User Part Number: UPN; alternate symbols: (R0402L,R0402L_ALT); part number: RES_SM-0,E003438,N/A,5,R0402; tolerance: 5
R4 R6 R327 = RES: Tolerance: 1; User Part Number: UPN; alternate symbols: (R0402L,R0402L_ALT); part number: RES_SM-1K,E003763,1/10W,1,R0402; tolerance: 1
R5 R28-R30 R35 R36 R38-R40 R50-R52 R72 R73 R312 R313 R330 R416 XR2 = RES: Tolerance: 1; User Part Number: UPN; alternate symbols: (R0402L,R0402L_ALT); part number: RES_SM-10K,E003751,1/10W,1,R0402; tolerance: 1
R7 = RES: Tolerance: 1; User Part Number: UPN; alternate symbols: (R0402L); part number: RES_SM-9.76K,E010026,1/16W,1,R0402; tolerance: 1; signal model: DEFAULT_RESISTOR_0.001OHM_1_2
R9 R10 R24 R25 = RES: Tolerance: 5; User Part Number: UPN; alternate symbols: (R0402L); part number: RES_SM-100K,E003464,1/10W,5,R0402; tolerance: 5
R11 R14 = RES: alternate symbols: (); part number: RES_SM-200,E004008,1/20W,1,R0201; tolerance: 1
R12 R13 = RES: alternate symbols: (); part number: RES_SM-62,E007221,1/20W,1,R0201; tolerance: 1
R15 = RES: Tolerance: 1; User Part Number: UPN; alternate symbols: (R0402L,R0402L_ALT); part number: RES_SM-100K,E003796,1/16W,1,R0402; tolerance: 1
R16 = RES: Tolerance: 1; User Part Number: UPN; alternate symbols: (R0402L); part number: RES_SM-49.9K,E026957,1/16W,1,R0402; tolerance: 1
R17 = RES: Tolerance: 1; User Part Number: UPN; alternate symbols: (R0402L); part number: RES_SM-0.2,E022868,1/6W,1,R0402; tolerance: 1
R18-R20 R22 R23 = RES: Tolerance: N/A; User Part Number: UPN; alternate symbols: (R0402L); part number: RES_SM-0,E025226,1/16W,N/A,R0402; tolerance: N/A
R21 = RES: Tolerance: 5; User Part Number: UPN; alternate symbols: (R0402L); part number: RES_SM-1,E019639,1/16W,5,R0402; tolerance: 5
R26 R32 = RES: alternate symbols: (); part number: RES_SM-100,E007239,1/20W,1,R0201; tolerance: 1
R27 = RES: Tolerance: 1; User Part Number: UPN; alternate symbols: (R0402L); part number: RES_SM-0.1,E017078,1/6W,1,R0402; tolerance: 1
R33 R34 = RES: Tolerance: 1; User Part Number: UPN; alternate symbols: (R0402L); part number: RES_SM-49.9,E003750,1/16W,1,R0402; tolerance: 1
R37 R612 R621 = RES: Tolerance: 1; User Part Number: UPN; alternate symbols: (R0402L); part number: RES_SM-100,E016329,1/10W,1,R0402; tolerance: 1
R43 = RES: Tolerance: 1; User Part Number: UPN; alternate symbols: (R0402L); part number: RES_SM-2.87K,E019883,1/16W,1,R0402; tolerance: 1
R44 = RES: Tolerance: 1; User Part Number: UPN; alternate symbols: (R0603L); part number: RES_SM-6.98K,E003680,1/10W,1,R0603; tolerance: 1
R45 = RES: Tolerance: 1; User Part Number: UPN; alternate symbols: (R0603L); part number: RES_SM-1.15K,E003930,1/10W,1,R0603; tolerance: 1
R46 = RES: Tolerance: 1; User Part Number: UPN; alternate symbols: (R0402L); part number: RES_SM-5.9K,E018094,1/10W,1,R0402; tolerance: 1
R53 R62 = RES: Tolerance: 1; User Part Number: UPN; alternate symbols: (R0402L,R0402L_ALT); part number: RES_SM-3.3K,E010034,1/10W,1,R0402; tolerance: 1
R56 = RES: Tolerance: 1; User Part Number: UPN; alternate symbols: (R0402L); part number: RES_SM-24.3K,E024557,1/16W,1,R0402; tolerance: 1
R57 = RES: Tolerance: 1; User Part Number: UPN; alternate symbols: (R0402L); part number: RES_SM-9.53K,E010032,1/16W,1,R0402; tolerance: 1
R58 = RES: Tolerance: 1; User Part Number: UPN; alternate symbols: (R0402L); part number: RES_SM-95.3K,E006343,1/16W,1,R0402; tolerance: 1
R59 = RES: Tolerance: 1; User Part Number: UPN; alternate symbols: (R0402L); part number: RES_SM-182K,E025180,1/10W,1,R0402; tolerance: 1
R60 R67 = RES: Tolerance: 1; User Part Number: UPN; alternate symbols: (R0402L); part number: RES_SM-49.9K,E004901,1/16W,1,R0402; tolerance: 1
R61 R611 = RES: Tolerance: 5; User Part Number: UPN; alternate symbols: (R0402L); part number: RES_SM-1.8K,E017175,1/10W,5,R0402; tolerance: 5
R64 = RES: Tolerance: 1; User Part Number: UPN; alternate symbols: (R0402L); part number: RES_SM-0,E010661,1/16W,1,R0402; tolerance: 1
R66 = RES: Tolerance: 1; User Part Number: UPN; alternate symbols: (R0402L); part number: RES_SM-261K,E010024,1/16W,1,R0402; tolerance: 1
R69 = RES: Tolerance: 5; User Part Number: UPN; alternate symbols: (R0402L); part number: RES_SM-51,E003442,1/16W,5,R0402; tolerance: 5
R74 = RES: Tolerance: 1; User Part Number: UPN; alternate symbols: (R0402L); part number: RES_SM-62K,E003786,1/16W,1,R0402; tolerance: 1
R75 = RES: Tolerance: 1; User Part Number: UPN; alternate symbols: (R0402L); part number: RES_SM-66.5K,E019641,1/16W,1,R0402; tolerance: 1
R88 = RES: alternate symbols: (); part number: RES_SM-20K,E004013,1/20W,1,R0201; tolerance: 1
R413 = RES: Tolerance: 1; User Part Number: UPN; alternate symbols: (R0402L); part number: RES_SM-31.6K,E019881,1/10W,1,R0402; tolerance: 1
R417 = RES: Tolerance: 1; User Part Number: UPN; alternate symbols: (R0402L); part number: RES_SM-680,E015602,1/10W,1,R0402; tolerance: 1
R419 = RES: Tolerance: 1; User Part Number: UPN; alternate symbols: (R0402L); part number: RES_SM-80.6K,E006346,1/16W,1,R0402; tolerance: 1
R420 = RES: Tolerance: 5; User Part Number: UPN; alternate symbols: (R0402L); part number: RES_SM-75K,E006752,1/16W,5,R0402; tolerance: 5
R423 = RES: Tolerance: 1; User Part Number: UPN; alternate symbols: (R0402L); part number: RES_SM-13.7K,E019610,1/16W,1,R0402; tolerance: 1
R424 = RES: Tolerance: 1; User Part Number: UPN; alternate symbols: (R0402L,R0402L_ALT); part number: RES_SM-20K,E003791,1/16W,1,R0402; tolerance: 1
R428 = RES: Tolerance: 1; User Part Number: UPN; alternate symbols: (R0402L); part number: RES_SM-330K,E025663,1/16W,1,R0402; tolerance: 1
R430 = RES: Tolerance: 1; User Part Number: UPN; alternate symbols: (R0402L); part number: RES_SM-412K,E020773,1/10W,1,R0402; tolerance: 1
R434 = RES: Tolerance: 5; User Part Number: UPN; alternate symbols: (R0402L); part number: RES_SM-110K,E022825,1/10W,5,R0402; tolerance: 5
R436 = RES: Tolerance: 1; User Part Number: UPN; alternate symbols: (R0402L); part number: RES_SM-62K,E021391,1/16W,1,R0402; tolerance: 1
R437 = RES: Tolerance: 1; User Part Number: UPN; alternate symbols: (R0402L); part number: RES_SM-1.5K,E003782,1/16W,1,R0402; tolerance: 1
R618 = RES: Tolerance: 0.1; User Part Number: UPN; alternate symbols: (R0402L); part number: RES_SM-5.1K,E010267,1/16W,0.1,R0402; tolerance: 0.1
R622 R623 R625 = RES: alternate symbols: (); part number: RES_SM-49.9,E007693,1/20W,1,R0201; tolerance: 1
SYNCN SYNCP SYSRFN SYSRFP = NCTESTPAD: Tolerance: N/A; User Part Number: UPN; alternate symbols: (); part number: NCTESTPAD_SM-TESTPAD,E012884,TPSMC30; tolerance: N/A
T1 = XFMRETC1_A_V2: Tolerance: N/A; User Part Number: UPN; alternate symbols: (); part number: XFMRETC1_A_V2_SM-TC1-1-43A+,E012306,AT224-1; tolerance: N/A
T33 = XFMRTCMXXXX_V3: Tolerance: N/A; User Part Number: UPN; alternate symbols: (); part number: XFMRTCMXXXX_V3_SM-TCM1-63AX+,E018203,TSML150W160H160; tolerance: N/A
TP21 TP43 = NCTESTPAD: Tolerance: N/A; User Part Number: UPN; alternate symbols: (); part number: NCTESTPAD_TH-TESTPAD,E013404,TPC65D45; tolerance: N/A
TP41 = CNTP1P: Tolerance: N/A; User Part Number: UPN; alternate symbols: (); part number: CNTP1P_TH-RED,E016323,CNKEY5001TP; tolerance: N/A
TP42 = CNTP1P: Tolerance: N/A; User Part Number: UPN; alternate symbols: (); part number: CNTP1P_TH-BLK,E015367,CNKEY5005-9TP; tolerance: N/A
TP64 = CNTP1P: Tolerance: N/A; User Part Number: UPN; alternate symbols: (); part number: CNTP1P_TH-BLK,E005347,CNKEY5001TP; tolerance: N/A
U1 = AD9162_V4: User Part Number: UPN; Tolerance: N/A; alternate symbols: (); part number: AD9162_V4_SM-AD9162BBCZ,E029000,BGA165_A; tolerance: N/A
U2 U3 = ADP176X: User Part Number: UPN; Tolerance: N/A; alternate symbols: (); part number: ADP176X_SM-ADP1761ACPZ-1.2,E026007,QFN16_3X3_PAD1_6X1_6; tolerance: N/A
U4 = ADM7160: User Part Number: UPN; Tolerance: N/A; alternate symbols: (); part number: ADM7160_SM-ADM7160AUJZ-3.3,E018670,TSOT-5; tolerance: N/A
U5 = ICHMC849LP4CE: Tolerance: N/A; User Part Number: UPN; alternate symbols: (); part number: ICHMC849LP4CE_SM-HMC849LP4CE,E017082,HMC849LP4CE; tolerance: N/A
U6 = ADM7150: Tolerance: N/A; User Part Number: UPN; alternate symbols: (); part number: ADM7150_SM-ADM7150ACPZ-5.0-R7,E018417,DFN8_3X3_PAD2_38X1_64; tolerance: N/A
U7 = AD9508: User Part Number: UPN; Tolerance: N/A; alternate symbols: (); part number: AD9508_SM-AD9508BCPZ,E015653,QFN24_4X4_PAD2_5X2_5; tolerance: N/A
U8 = LINLTC2928: User Part Number: UPN; Tolerance: N/A; alternate symbols: (); part number: LINLTC2928_SM-LTC2928CUHF#PBF,E028640,QFN38_7X5_PAD5_15X3_15; tolerance: N/A
U9 = ICHMC362S8G: Tolerance: N/A; User Part Number: UPN; alternate symbols: (); part number: ICHMC362S8G_SM-HMC362S8GE,E001995,SO8NB-3-PAD; tolerance: N/A
U10 = ADP5054: User Part Number: UPN; Tolerance: N/A; alternate symbols: (); part number: ADP5054_SM-ADP5054ACPZ,E019222,QFN48_7X7_PAD5_6X5_6; tolerance: N/A
U11 = ADP5073: User Part Number: UPN; Tolerance: N/A; alternate symbols: (); part number: ADP5073_SM-ADP5073ACPZ,E020650,QFN16_3X3_PAD1_6X1_6; tolerance: N/A
U12 = ADP7183: User Part Number: UPN; Tolerance: N/A; alternate symbols: (); part number: ADP7183_SM-ADP7183ACPZN1.2-R7,E026787,DFN8_2X2_PAD1_5X1; tolerance: N/A
U13 = ADM7154: Tolerance: N/A; User Part Number: UPN; alternate symbols: (); part number: ADM7154_SM-ADM7154ACPZ-2.5,E020759,DFN8_3X3_PAD2_44X1_6_A; tolerance: N/A
U14 U18 U19 = ADM7154: User Part Number: UPN; Tolerance: N/A; alternate symbols: (); part number: ADM7154_SM-ADM7154ACPZ-3.3,E020267,DFN8_3X3_PAD2_38X1_64; tolerance: N/A
U15 = ADF4355: Tolerance: N/A; User Part Number: UPN; alternate symbols: (); part number: ADF4355_SM-ADF4355BCPZ,E022645,QFN32_5X5_PAD3_6X3_6; tolerance: N/A
U16 = ADCLK914: User Part Number: UPN; Tolerance: N/A; alternate symbols: (); part number: ADCLK914_SM-ADCLK914BCPZ,E010058,QFN16_3X3_PAD1_5X1_5; tolerance: N/A
U17 = ADM7150: User Part Number: UPN; Tolerance: N/A; alternate symbols: (); part number: ADM7150_SM-ADM7150ACPZ-5.0-R7,E018417,DFN8_3X3_PAD2_38X1_64; tolerance: N/A
U20 = ICPIC18F2XJ50: User Part Number: UPN; Tolerance: N/A; alternate symbols: (); part number: ICPIC18F2XJ50_SM-PIC18F24J50-I/ML,E014088,QFN28_6X6_PAD3_7X3_7; tolerance: N/A
U21 U22 = ICFXL4TD245: Tolerance: N/A; User Part Number: UPN; alternate symbols: (); part number: ICFXL4TD245_SM-FXL4TD245BQX,E014936,DQFN16_3_5X2_5_PAD2_15X1_15; tolerance: N/A
U23 = ICM24CXX: Tolerance: N/A; User Part Number: UPN; alternate symbols: (); part number: ICM24CXX_SM-M24C02-RDW6TP,E027045,TSSOP8; tolerance: N/A
XC5 XC6 = CAP: Tolerance: 10; User Part Number: UPN; alternate symbols: (); part number: CAP_SM-0.1UF,25V,10,E007204,C0603; tolerance: 10
XC12 = CAP: Tolerance: 20; User Part Number: UPN; alternate symbols: (); part number: CAP_SM-10UF,6.3V,20,E007143,C0603; tolerance: 20
XCR1 = DIOLED: User Part Number: UPN; Tolerance: N/A; alternate symbols: (); part number: DIOLED_SM-LB Q39E-N1OO-35-1,N/A,N/A,E028471,LED0603H12; tolerance: N/A
XP1 = CN6P: User Part Number: UPN; Tolerance: N/A; alternate symbols: (); part number: CN6P_TH-TSW-106-08-G-S,E000872,CNBERG1X6H205LD36; tolerance: N/A
XP2 = CN5P_3GND: User Part Number: UPN; Tolerance: N/A; alternate symbols: (); part number: CN5P_3GND_TH-2041517-1,E021058,CNTE2041517-1; tolerance: N/A
XR6 = RES: Tolerance: 1; User Part Number: UPN; alternate symbols: (); part number: RES_SM-330,E004065,1/8W,1,R1206; tolerance: 1
Y61 = XTALOSC6P_V10: User Part Number: UPN; Tolerance: 5; alternate symbols: (); part number: XTALOSC6P_V10_SM-120.00MEGHZ,E024318,YSML276W197H63; tolerance: 5

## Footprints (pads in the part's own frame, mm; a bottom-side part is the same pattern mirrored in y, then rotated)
AT224-1
  rect 0.762x1.651 smd: 1(-1.27,1.587) 2(0,1.587) 3(1.27,1.587) 4(1.27,-1.587) 6(-1.27,-1.587)
BGA165_A
  round 0.254 smd: A1(-3.5,-3.5) A2(-3.5,-3) A3(-3.5,-2.5) A4(-3.5,-2) A5(-3.5,-1.5) A6(-3.5,-1) A7(-3.5,-0.5) A8(-3.5,0) A9(-3.5,0.5) A10(-3.5,1) A11(-3.5,1.5) A12(-3.5,2) A13(-3.5,2.5) A14(-3.5,3) A15(-3.5,3.5) B1(-3,-3.5) B2(-3,-3) B3(-3,-2.5) B4(-3,-2) B5(-3,-1.5) B6(-3,-1) B7(-3,-0.5) B8(-3,0) B9(-3,0.5) B10(-3,1) B11(-3,1.5) B12(-3,2) B13(-3,2.5) B14(-3,3) B15(-3,3.5) C1(-2.5,-3.5) C2(-2.5,-3) C4(-2.5,-2) C5(-2.5,-1.5) C6(-2.5,-1) C7(-2.5,-0.5) C8(-2.5,0) C9(-2.5,0.5) C10(-2.5,1) C11(-2.5,1.5) C12(-2.5,2) C14(-2.5,3) C15(-2.5,3.5) D1(-2,-3.5) D2(-2,-3) D3(-2,-2.5) D13(-2,2.5) D14(-2,3) D15(-2,3.5) E1(-1.5,-3.5) E2(-1.5,-3) E3(-1.5,-2.5) E13(-1.5,2.5) E14(-1.5,3) E15(-1.5,3.5) F1(-1,-3.5) F2(-1,-3) F3(-1,-2.5) F6(-1,-1) F7(-1,-0.5) F8(-1,0) F9(-1,0.5) F10(-1,1) F13(-1,2.5) F14(-1,3) F15(-1,3.5) G1(-0.5,-3.5) G2(-0.5,-3) G3(-0.5,-2.5) G6(-0.5,-1) G7(-0.5,-0.5) G8(-0.5,0) G9(-0.5,0.5) G10(-0.5,1) G13(-0.5,2.5) G14(-0.5,3) G15(-0.5,3.5) H1(0,-3.5) H2(0,-3) H3(0,-2.5) H6(0,-1) H7(0,-0.5) H8(0,0) H9(0,0.5) H10(0,1) H13(0,2.5) H14(0,3) H15(0,3.5) J1(0.5,-3.5) J2(0.5,-3) J3(0.5,-2.5) J6(0.5,-1) J7(0.5,-0.5) J8(0.5,0) J9(0.5,0.5) J10(0.5,1) J13(0.5,2.5) J14(0.5,3) J15(0.5,3.5) K1(1,-3.5) K2(1,-3) K3(1,-2.5) K6(1,-1) K7(1,-0.5) K8(1,0) K9(1,0.5) K10(1,1) K13(1,2.5) K14(1,3) K15(1,3.5) L1(1.5,-3.5) L2(1.5,-3) L3(1.5,-2.5) L13(1.5,2.5) L14(1.5,3) L15(1.5,3.5) M1(2,-3.5) M2(2,-3) M3(2,-2.5) M13(2,2.5) M14(2,3) M15(2,3.5) N1(2.5,-3.5) N2(2.5,-3) N4(2.5,-2) N5(2.5,-1.5) N6(2.5,-1) N7(2.5,-0.5) N8(2.5,0) N9(2.5,0.5) N10(2.5,1) N11(2.5,1.5) N12(2.5,2) N14(2.5,3) N15(2.5,3.5) P1(3,-3.5) P2(3,-3) P3(3,-2.5) P4(3,-2) P5(3,-1.5) P6(3,-1) P7(3,-0.5) P8(3,0) P9(3,0.5) P10(3,1) P11(3,1.5) P12(3,2) P13(3,2.5) P14(3,3) P15(3,3.5) R1(3.5,-3.5) R2(3.5,-3) R3(3.5,-2.5) R4(3.5,-2) R5(3.5,-1.5) R6(3.5,-1) R7(3.5,-0.5) R8(3.5,0) R9(3.5,0.5) R10(3.5,1) R11(3.5,1.5) R12(3.5,2) R13(3.5,2.5) R14(3.5,3) R15(3.5,3.5)
C0201
  rect 0.305x0.406 smd: 1(-0.318,0) 2(0.318,0)
C0402
  rect 0.889x0.813 smd: 1(-0.635,0) 2(0.635,0)
C0508IDC
  rect 0.305x0.635 smd: 1(-0.762,-0.635) 2(-0.254,-0.635) 3(0.254,-0.635) 4(0.762,-0.635) 5(0.762,0.635) 6(0.254,0.635) 7(-0.254,0.635) 8(-0.762,0.635)
C0603
  rect 1.092x1.194 smd: 1(-0.851,0) 2(0.851,0)
C0803H60
  rect 1.295x0.635 smd: 1(-0.953,0) 2(0.953,0)
C0805
  rect 1.295x1.6 smd: 1(-0.953,0) 2(0.953,0)
C0805H60
  rect 1.295x1.6 smd: 1(-0.953,0) 2(0.953,0)
C1206
  rect 1.6x2.007 smd: 1(-1.397,0) 2(1.397,0)
C1206H71
  rect 1.6x2.007 smd: 1(-1.397,0) 2(1.397,0)
C1210-2
  rect 1.575x2.692 smd: 1(-1.397,0) 2(1.397,0)
C3216
  rect 2.032x1.194 smd: N(1.397,0) P(-1.397,0)
C3528
  rect 2.032x2.21 smd: N(1.524,0) P(-1.524,0)
CNBERG1X6H205LD36
  rect 1.651x1.651 hole 1.143: 1(0,0)
  round 1.651 hole 1.143: 2(2.54,0) 3(5.08,0) 4(7.62,0) 5(10.16,0) 6(12.7,0)
CNBERG69157-102
  rect 1.524x1.524 hole 1.016: 1(0,0)
  round 1.524 hole 1.016: 2(2.54,0)
CNJOHNSON142-0711-201
  round 1.727 smd: 1(0,0)
  custom 0.591x0.591 smd: 2(-2.807,0) 3(2.807,0)
CNKEY5001TP
  round 1.524 hole 1.016: 1(0,0)
CNKEY5005-9TP
  round 2.159 hole 1.6: 1(0,0)
CNMOLEX22-28-4033
  rect 1.524x1.524 hole 1.016: 1(0,0)
  round 1.524 hole 1.016: 2(2.54,0) 3(5.08,0)
CNSAMTECASP-134488-01
  round 2.54 hole 1.27 unplated: (-2.426,5.715) (51.956,8.763)
  round 0.635 smd: A1(0,0) A2(1.27,0) A3(2.54,0) A4(3.81,0) A5(5.08,0) A6(6.35,0) A7(7.62,0) A8(8.89,0) A9(10.16,0) A10(11.43,0) A11(12.7,0) A12(13.97,0) A13(15.24,0) A14(16.51,0) A15(17.78,0) A16(19.05,0) A17(20.32,0) A18(21.59,0) A19(22.86,0) A20(24.13,0) A21(25.4,0) A22(26.67,0) A23(27.94,0) A24(29.21,0) A25(30.48,0) A26(31.75,0) A27(33.02,0) A28(34.29,0) A29(35.56,0) A30(36.83,0) A31(38.1,0) A32(39.37,0) A33(40.64,0) A34(41.91,0) A35(43.18,0) A36(44.45,0) A37(45.72,0) A38(46.99,0) A39(48.26,0) A40(49.53,0) B1(0,1.27) B2(1.27,1.27) B3(2.54,1.27) B4(3.81,1.27) B5(5.08,1.27) B6(6.35,1.27) B7(7.62,1.27) B8(8.89,1.27) B9(10.16,1.27) B10(11.43,1.27) B11(12.7,1.27) B12(13.97,1.27) B13(15.24,1.27) B14(16.51,1.27) B15(17.78,1.27) B16(19.05,1.27) B17(20.32,1.27) B18(21.59,1.27) B19(22.86,1.27) B20(24.13,1.27) B21(25.4,1.27) B22(26.67,1.27) B23(27.94,1.27) B24(29.21,1.27) B25(30.48,1.27) B26(31.75,1.27) B27(33.02,1.27) B28(34.29,1.27) B29(35.56,1.27) B30(36.83,1.27) B31(38.1,1.27) B32(39.37,1.27) B33(40.64,1.27) B34(41.91,1.27) B35(43.18,1.27) B36(44.45,1.27) B37(45.72,1.27) B38(46.99,1.27) B39(48.26,1.27) B40(49.53,1.27) C1(0,2.54) C2(1.27,2.54) C3(2.54,2.54) C4(3.81,2.54) C5(5.08,2.54) C6(6.35,2.54) C7(7.62,2.54) C8(8.89,2.54) C9(10.16,2.54) C10(11.43,2.54) C11(12.7,2.54) C12(13.97,2.54) C13(15.24,2.54) C14(16.51,2.54) C15(17.78,2.54) C16(19.05,2.54) C17(20.32,2.54) C18(21.59,2.54) C19(22.86,2.54) C20(24.13,2.54) C21(25.4,2.54) C22(26.67,2.54) C23(27.94,2.54) C24(29.21,2.54) C25(30.48,2.54) C26(31.75,2.54) C27(33.02,2.54) C28(34.29,2.54) C29(35.56,2.54) C30(36.83,2.54) C31(38.1,2.54) C32(39.37,2.54) C33(40.64,2.54) C34(41.91,2.54) C35(43.18,2.54) C36(44.45,2.54) C37(45.72,2.54) C38(46.99,2.54) C39(48.26,2.54) C40(49.53,2.54) D1(0,3.81) D2(1.27,3.81) D3(2.54,3.81) D4(3.81,3.81) D5(5.08,3.81) D6(6.35,3.81) D7(7.62,3.81) D8(8.89,3.81) D9(10.16,3.81) D10(11.43,3.81) D11(12.7,3.81) D12(13.97,3.81) D13(15.24,3.81) D14(16.51,3.81) D15(17.78,3.81) D16(19.05,3.81) D17(20.32,3.81) D18(21.59,3.81) D19(22.86,3.81) D20(24.13,3.81) D21(25.4,3.81) D22(26.67,3.81) D23(27.94,3.81) D24(29.21,3.81) D25(30.48,3.81) D26(31.75,3.81) D27(33.02,3.81) D28(34.29,3.81) D29(35.56,3.81) D30(36.83,3.81) D31(38.1,3.81) D32(39.37,3.81) D33(40.64,3.81) D34(41.91,3.81) D35(43.18,3.81) D36(44.45,3.81) D37(45.72,3.81) D38(46.99,3.81) D39(48.26,3.81) D40(49.53,3.81) E1(0,5.08) E2(1.27,5.08) E3(2.54,5.08) E4(3.81,5.08) E5(5.08,5.08) E6(6.35,5.08) E7(7.62,5.08) E8(8.89,5.08) E9(10.16,5.08) E10(11.43,5.08) E11(12.7,5.08) E12(13.97,5.08) E13(15.24,5.08) E14(16.51,5.08) E15(17.78,5.08) E16(19.05,5.08) E17(20.32,5.08) E18(21.59,5.08) E19(22.86,5.08) E20(24.13,5.08) E21(25.4,5.08) E22(26.67,5.08) E23(27.94,5.08) E24(29.21,5.08) E25(30.48,5.08) E26(31.75,5.08) E27(33.02,5.08) E28(34.29,5.08) E29(35.56,5.08) E30(36.83,5.08) E31(38.1,5.08) E32(39.37,5.08) E33(40.64,5.08) E34(41.91,5.08) E35(43.18,5.08) E36(44.45,5.08) E37(45.72,5.08) E38(46.99,5.08) E39(48.26,5.08) E40(49.53,5.08) F1(0,6.35) F2(1.27,6.35) F3(2.54,6.35) F4(3.81,6.35) F5(5.08,6.35) F6(6.35,6.35) F7(7.62,6.35) F8(8.89,6.35) F9(10.16,6.35) F10(11.43,6.35) F11(12.7,6.35) F12(13.97,6.35) F13(15.24,6.35) F14(16.51,6.35) F15(17.78,6.35) F16(19.05,6.35) F17(20.32,6.35) F18(21.59,6.35) F19(22.86,6.35) F20(24.13,6.35) F21(25.4,6.35) F22(26.67,6.35) F23(27.94,6.35) F24(29.21,6.35) F25(30.48,6.35) F26(31.75,6.35) F27(33.02,6.35) F28(34.29,6.35) F29(35.56,6.35) F30(36.83,6.35) F31(38.1,6.35) F32(39.37,6.35) F33(40.64,6.35) F34(41.91,6.35) F35(43.18,6.35) F36(44.45,6.35) F37(45.72,6.35) F38(46.99,6.35) F39(48.26,6.35) F40(49.53,6.35) G1(0,7.62) G2(1.27,7.62) G3(2.54,7.62) G4(3.81,7.62) G5(5.08,7.62) G6(6.35,7.62) G7(7.62,7.62) G8(8.89,7.62) G9(10.16,7.62) G10(11.43,7.62) G11(12.7,7.62) G12(13.97,7.62) G13(15.24,7.62) G14(16.51,7.62) G15(17.78,7.62) G16(19.05,7.62) G17(20.32,7.62) G18(21.59,7.62) G19(22.86,7.62) G20(24.13,7.62) G21(25.4,7.62) G22(26.67,7.62) G23(27.94,7.62) G24(29.21,7.62) G25(30.48,7.62) G26(31.75,7.62) G27(33.02,7.62) G28(34.29,7.62) G29(35.56,7.62) G30(36.83,7.62) G31(38.1,7.62) G32(39.37,7.62) G33(40.64,7.62) G34(41.91,7.62) G35(43.18,7.62) G36(44.45,7.62) G37(45.72,7.62) G38(46.99,7.62) G39(48.26,7.62) G40(49.53,7.62) H1(0,8.89) H2(1.27,8.89) H3(2.54,8.89) H4(3.81,8.89) H5(5.08,8.89) H6(6.35,8.89) H7(7.62,8.89) H8(8.89,8.89) H9(10.16,8.89) H10(11.43,8.89) H11(12.7,8.89) H12(13.97,8.89) H13(15.24,8.89) H14(16.51,8.89) H15(17.78,8.89) H16(19.05,8.89) H17(20.32,8.89) H18(21.59,8.89) H19(22.86,8.89) H20(24.13,8.89) H21(25.4,8.89) H22(26.67,8.89) H23(27.94,8.89) H24(29.21,8.89) H25(30.48,8.89) H26(31.75,8.89) H27(33.02,8.89) H28(34.29,8.89) H29(35.56,8.89) H30(36.83,8.89) H31(38.1,8.89) H32(39.37,8.89) H33(40.64,8.89) H34(41.91,8.89) H35(43.18,8.89) H36(44.45,8.89) H37(45.72,8.89) H38(46.99,8.89) H39(48.26,8.89) H40(49.53,8.89) J1(0,10.16) J2(1.27,10.16) J3(2.54,10.16) J4(3.81,10.16) J5(5.08,10.16) J6(6.35,10.16) J7(7.62,10.16) J8(8.89,10.16) J9(10.16,10.16) J10(11.43,10.16) J11(12.7,10.16) J12(13.97,10.16) J13(15.24,10.16) J14(16.51,10.16) J15(17.78,10.16) J16(19.05,10.16) J17(20.32,10.16) J18(21.59,10.16) J19(22.86,10.16) J20(24.13,10.16) J21(25.4,10.16) J22(26.67,10.16) J23(27.94,10.16) J24(29.21,10.16) J25(30.48,10.16) J26(31.75,10.16) J27(33.02,10.16) J28(34.29,10.16) J29(35.56,10.16) J30(36.83,10.16) J31(38.1,10.16) J32(39.37,10.16) J33(40.64,10.16) J34(41.91,10.16) J35(43.18,10.16) J36(44.45,10.16) J37(45.72,10.16) J38(46.99,10.16) J39(48.26,10.16) J40(49.53,10.16) K1(0,11.43) K2(1.27,11.43) K3(2.54,11.43) K4(3.81,11.43) K5(5.08,11.43) K6(6.35,11.43) K7(7.62,11.43) K8(8.89,11.43) K9(10.16,11.43) K10(11.43,11.43) K11(12.7,11.43) K12(13.97,11.43) K13(15.24,11.43) K14(16.51,11.43) K15(17.78,11.43) K16(19.05,11.43) K17(20.32,11.43) K18(21.59,11.43) K19(22.86,11.43) K20(24.13,11.43) K21(25.4,11.43) K22(26.67,11.43) K23(27.94,11.43) K24(29.21,11.43) K25(30.48,11.43) K26(31.75,11.43) K27(33.02,11.43) K28(34.29,11.43) K29(35.56,11.43) K30(36.83,11.43) K31(38.1,11.43) K32(39.37,11.43) K33(40.64,11.43) K34(41.91,11.43) K35(43.18,11.43) K36(44.45,11.43) K37(45.72,11.43) K38(46.99,11.43) K39(48.26,11.43) K40(49.53,11.43)
